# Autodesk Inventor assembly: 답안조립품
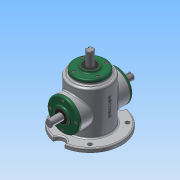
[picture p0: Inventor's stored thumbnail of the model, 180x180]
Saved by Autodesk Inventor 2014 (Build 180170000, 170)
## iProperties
Created: 2018-04
Part Number: 답안조립품
Document SubType Name: Assembly
Designer: user
Author: user
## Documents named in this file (17)
- C:\Users\user\Desktop\480407V1015\답안조립품.iam
- C:\Users\user\Desktop\480407V1015\본체.ipt
- C:\Users\user\Desktop\480407V1015\메인 베벨기어.ipt
- C:\Users\user\Desktop\480407V1015\메인 축.ipt
- 메인 축.ipt
- C:\Users\user\Desktop\480407V1015\베어링 6203.ipt
- C:\Users\user\Desktop\480407V1015\볼트 M4.ipt
- 볼트 M4.ipt
- C:\Users\user\Desktop\480407V1015\서브 베벨기어.ipt
- C:\Users\user\Desktop\480407V1015\서브 축.ipt
- 서브 축.ipt
- C:\Users\user\Desktop\480407V1015\스퍼기어.iam
- C:\Users\user\Desktop\480407V1015\오일 실.ipt
- 오일 실.ipt
- C:\Users\user\Desktop\480407V1015\커버.ipt
- C:\Users\user\Desktop\480407V1015\키 4x4.ipt
- C:\Users\user\Desktop\480407V1015\키 5x5.ipt
